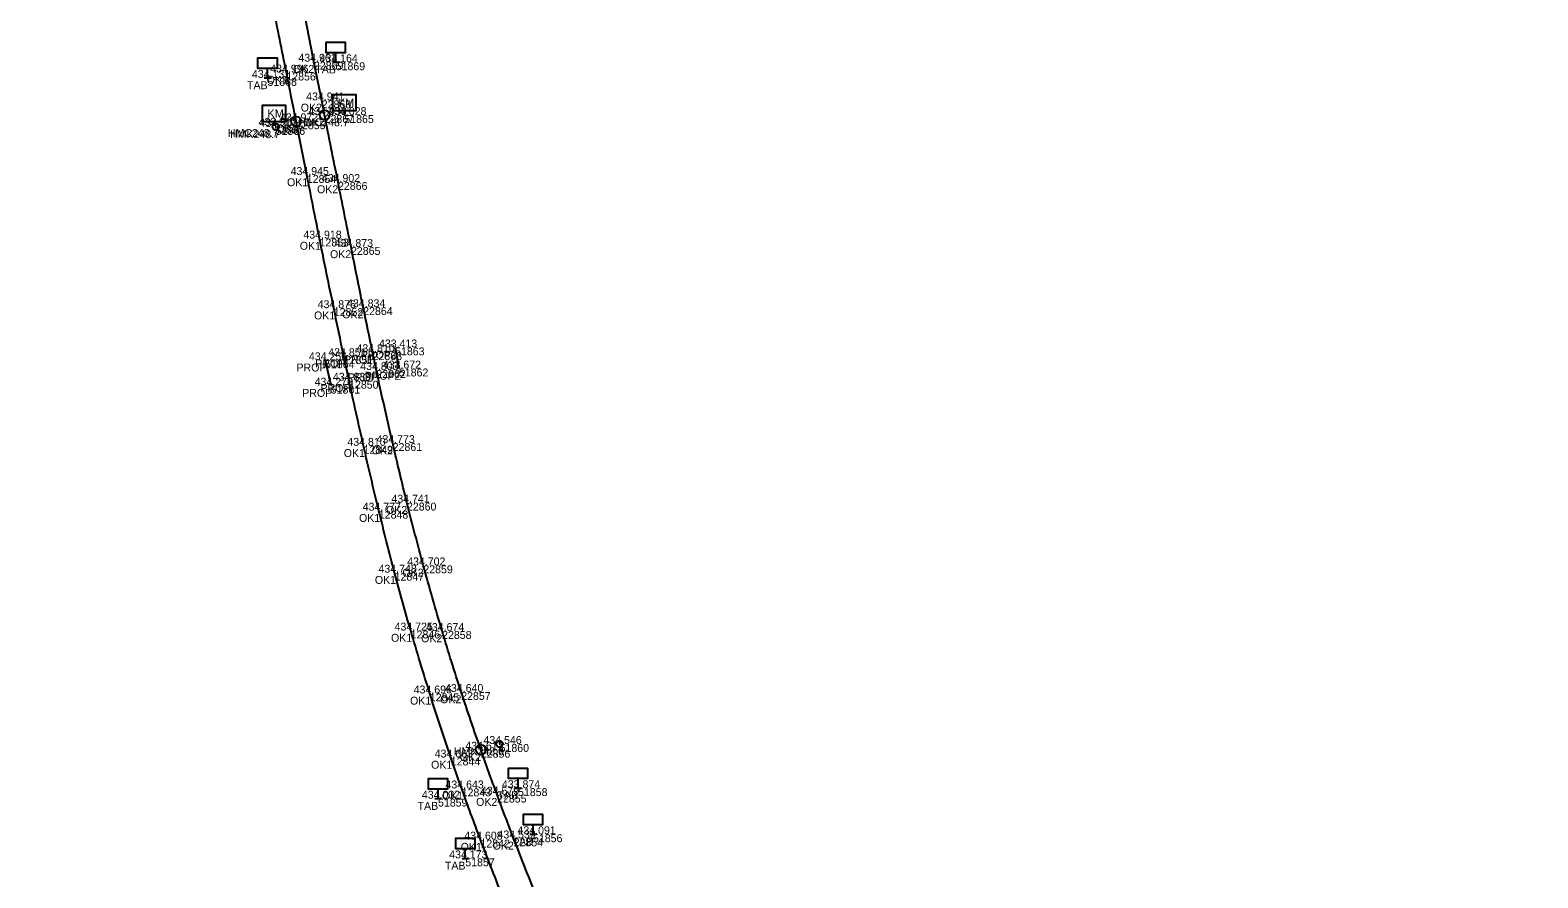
# Model space of a CAD drawing. Extents: x -678609 to -677678, y -1092434 to -1090394.
# Drawn here: x -678600.8 to -678372.1, y -1090904.4 to -1090775.9 of the extents above; entities that cross this region are included whole.
import ezdxf

# ---------------------------------------------------------------- set-up
doc = ezdxf.new("R2010")
doc.units = 0
for name, color, linetype in [('Vrstva 1', 7, 'Continuous'), ('Vrstva 19', 7, 'Continuous'), ('Vrstva 51', 7, 'Continuous'), ('Vrstva 60', 7, 'Continuous'), ('Vrstva 61', 7, 'Continuous'), ('Vrstva 62', 7, 'Continuous'), ('Vrstva 7', 7, 'Continuous')]:
    doc.layers.add(name, color=color, linetype=linetype)

msp = doc.modelspace()

# ---------------------------------------------------------------- linework, layer by layer
at = {"layer": 'Vrstva 1'}
for points in [[(-677965.5, -1092428.88), (-677967.8, -1092425.54), (-677972.06, -1092419.07), (-677977.32, -1092410.57), (-677981.84, -1092402.75), (-677986.7, -1092393.7), (-677991.48, -1092384.16), (-677995.99, -1092374.55), (-678000.17, -1092365.13), (-678004.02, -1092356.1), (-678007.82, -1092346.9), (-678011.74, -1092337.16), (-678015.49, -1092327.76), (-678018.88, -1092319.21), (-678022.34, -1092310.49), (-678025.4, -1092302.78), (-678026.46, -1092300.1), (-678028.08, -1092296.04), (-678031.51, -1092287.37), (-678035.08, -1092278.36), (-678038.67, -1092269.33), (-678042.19, -1092260.44), (-678045.92, -1092251.04), (-678049.17, -1092242.84), (-678052.72, -1092233.88), (-678056.52, -1092224.29), (-678060.13, -1092215.17), (-678063.85, -1092205.78), (-678067.58, -1092196.38), (-678071.23, -1092187.17), (-678074.63, -1092178.59), (-678078.07, -1092169.9), (-678081.19, -1092162.05), (-678084.71, -1092153.16), (-678085.21, -1092151.9), (-678088.66, -1092143.2), (-678090.49, -1092138.62), (-678093.75, -1092130.39), (-678097.35, -1092121.32), (-678101.03, -1092112.07), (-678104.65, -1092102.94), (-678108.08, -1092094.3), (-678111.85, -1092084.82), (-678115.34, -1092076.03), (-678118.88, -1092067.13), (-678122.7, -1092057.52), (-678126.45, -1092048.08), (-678130.12, -1092038.85), (-678134.04, -1092029), (-678137.7, -1092019.78), (-678141.32, -1092010.68), (-678144.94, -1092001.55), (-678148.54, -1091992.51), (-678152.22, -1091983.22), (-678155.78, -1091974.26), (-678159.37, -1091965.23), (-678163.15, -1091955.67), (-678166.8, -1091946.49), (-678170.64, -1091936.84), (-678174.45, -1091927.39), (-678178.21, -1091918.23), (-678182.03, -1091909.19), (-678185.86, -1091900.36), (-678190.3, -1091890.41), (-678194.61, -1091881.04), (-678198.42, -1091872.99), (-678201.55, -1091866.52), (-678205.76, -1091857.98), (-678210.04, -1091849.52), (-678214.14, -1091841.6), (-678218.68, -1091833.02), (-678223.39, -1091824.3), (-678228.11, -1091815.74), (-678232.89, -1091807.24), (-678237.68, -1091798.82), (-678242.57, -1091790.27), (-678247.48, -1091781.7), (-678252.5, -1091772.96), (-678257.41, -1091764.41), (-678262.3, -1091755.91), (-678267.38, -1091747.08), (-678272.06, -1091738.95), (-678276.67, -1091730.93), (-678281, -1091723.4), (-678285.64, -1091715.33), (-678290.57, -1091706.75), (-678295.17, -1091698.74), (-678299.18, -1091691.75), (-678304.61, -1091682.28), (-678309.18, -1091674.33), (-678309.94, -1091673.01), (-678310.56, -1091671.92), (-678316.58, -1091661.44), (-678321.55, -1091652.79), (-678326.07, -1091644.94), (-678331.1, -1091636.19), (-678336.13, -1091627.42), (-678341.16, -1091618.67), (-678346.24, -1091609.83), (-678351.2, -1091601.19), (-678356.26, -1091592.39), (-678361.27, -1091583.68), (-678366.29, -1091574.95), (-678371.38, -1091566.09), (-678376.48, -1091557.23), (-678380.94, -1091549.47), (-678384.95, -1091542.5), (-678389.88, -1091533.92), (-678391.41, -1091531.24), (-678395.31, -1091524.46), (-678398.31, -1091519.22), (-678402.19, -1091512.46), (-678406.98, -1091504.09), (-678412.06, -1091495.21), (-678417.07, -1091486.44), (-678421.59, -1091478.47), (-678426.39, -1091469.86), (-678431.19, -1091461.01), (-678435.59, -1091452.6), (-678440.54, -1091442.69), (-678444.84, -1091433.53), (-678448.93, -1091424.07), (-678452.67, -1091414.65), (-678456.15, -1091404.93), (-678459.23, -1091395.35), (-678461.83, -1091386.29), (-678463.33, -1091380.53), (-678465.42, -1091371.56), (-678467.31, -1091362.18), (-678468.87, -1091352.97), (-678470.15, -1091343.72), (-678471.15, -1091334.55), (-678471.89, -1091325.25), (-678472.38, -1091315.14), (-678472.53, -1091305.81), (-678472.39, -1091295.81), (-678471.98, -1091285.84), (-678471.34, -1091275.9), (-678470.53, -1091266.07), (-678469.61, -1091256.67), (-678468.46, -1091246.14), (-678467.2, -1091235.36), (-678466.06, -1091225.73), (-678464.97, -1091216.57), (-678463.79, -1091206.63), (-678462.6, -1091196.46), (-678461.48, -1091186.51), (-678460.53, -1091177.26), (-678460.07, -1091172.27), (-678459.6, -1091166.76), (-678458.93, -1091157.15), (-678458.54, -1091149.43), (-678458.26, -1091139.81), (-678458.24, -1091130.03), (-678458.46, -1091121.76), (-678458.96, -1091112.72), (-678459.56, -1091105.42), (-678460.03, -1091100.7), (-678460.44, -1091097.18), (-678461.42, -1091089.83), (-678462.92, -1091080.59), (-678464.88, -1091070.5), (-678465.87, -1091066.01), (-678468.24, -1091056.34), (-678470.96, -1091046.62), (-678473.78, -1091037.66), (-678476.99, -1091028.33), (-678480.32, -1091019.35), (-678483.95, -1091010.17), (-678487.77, -1091000.93), (-678492.09, -1090990.94), (-678495.91, -1090982.33), (-678497.23, -1090979.39), (-678500.62, -1090971.85), (-678504.73, -1090962.75), (-678508.48, -1090954.44), (-678512.89, -1090944.72), (-678517.19, -1090935.17), (-678521.19, -1090926.12), (-678525.01, -1090917.23), (-678528.92, -1090907.75), (-678532.48, -1090898.64), (-678535.33, -1090890.88), (-678536.98, -1090886.19), (-678540.17, -1090876.47), (-678543.06, -1090866.93), (-678545.5, -1090858.15), (-678547.9, -1090848.75), (-678550.22, -1090838.91), (-678552.41, -1090829.04), (-678553.21, -1090825.32), (-678554.73, -1090818.04), (-678556.89, -1090807.48), (-678558.82, -1090797.84), (-678560.45, -1090789.69), (-678561.92, -1090782.3), (-678563.92, -1090772.26), (-678565.62, -1090763.66), (-678567.4, -1090754.78), (-678569.24, -1090745.59), (-678571.09, -1090736.37), (-678573.01, -1090726.79), (-678574.94, -1090717.24), (-678576.9, -1090707.5), (-678578.79, -1090698.06), (-678580.69, -1090688.61), (-678582.63, -1090679), (-678584.57, -1090669.32), (-678586.61, -1090659.12), (-678588.6, -1090649.18), (-678590.47, -1090639.75), (-678592.41, -1090629.68), (-678594.08, -1090620.48), (-678595.57, -1090611.73), (-678596.96, -1090602.7), (-678598.18, -1090593.61), (-678598.92, -1090587.15), (-678599.86, -1090577.04), (-678600.45, -1090567.62), (-678600.74, -1090558.34), (-678600.75, -1090549.35), (-678600.47, -1090539.84), (-678599.88, -1090530.15), (-678599.15, -1090521.99), (-678598.15, -1090513.61), (-678597.58, -1090509.5), (-678596.28, -1090501.33), (-678594.49, -1090491.96), (-678592.38, -1090482.44), (-678589.8, -1090472.45), (-678586.94, -1090462.72), (-678583.68, -1090452.87), (-678579.95, -1090442.85), (-678576.03, -1090433.29), (-678571.81, -1090423.92), (-678567.43, -1090415), (-678562.94, -1090406.55), (-678558.47, -1090398.73), (-678556.06, -1090394.72)], [(-677960.41, -1092428.88), (-677963.18, -1092424.89), (-677968.58, -1092416.71), (-677973.83, -1092408.16), (-677978.65, -1092399.73), (-677983.17, -1092391.19), (-677987.58, -1092382.29), (-677991.66, -1092373.51), (-677995.54, -1092364.73), (-677999.48, -1092355.45), (-678003, -1092346.86), (-678006.4, -1092338.41), (-678008.07, -1092334.22), (-678011.06, -1092326.67), (-678014.79, -1092317.28), (-678018.17, -1092308.77), (-678021.37, -1092300.71), (-678022.15, -1092298.75), (-678025.47, -1092290.39), (-678029, -1092281.48), (-678032.79, -1092271.95), (-678036.42, -1092262.78), (-678040.08, -1092253.55), (-678043.64, -1092244.58), (-678046.8, -1092236.63), (-678050.2, -1092228.09), (-678054.05, -1092218.4), (-678057.87, -1092208.77), (-678061.64, -1092199.28), (-678064.93, -1092190.99), (-678068.51, -1092181.96), (-678072.17, -1092172.75), (-678076, -1092163.12), (-678079.45, -1092154.42), (-678082.71, -1092146.18), (-678084.42, -1092141.9), (-678086.21, -1092137.37), (-678089.72, -1092128.54), (-678093.32, -1092119.46), (-678097.16, -1092109.8), (-678100.72, -1092100.82), (-678103.85, -1092092.93), (-678107.35, -1092084.1), (-678110.92, -1092075.12), (-678114.45, -1092066.22), (-678118.41, -1092056.23), (-678122.02, -1092047.13), (-678125.64, -1092038.01), (-678129.26, -1092028.91), (-678132.87, -1092019.79), (-678136.68, -1092010.21), (-678140.28, -1092001.13), (-678143.89, -1091992.04), (-678147.54, -1091982.83), (-678151.47, -1091972.91), (-678155.19, -1091963.55), (-678158.5, -1091955.23), (-678162.14, -1091946.1), (-678165.94, -1091936.55), (-678169.61, -1091927.42), (-678172.98, -1091919.18), (-678176.44, -1091910.89), (-678180.32, -1091901.84), (-678184.49, -1091892.39), (-678188.93, -1091882.59), (-678193.21, -1091873.41), (-678197.78, -1091863.91), (-678202.15, -1091855.03), (-678206.56, -1091846.3), (-678211.05, -1091837.64), (-678215.66, -1091828.96), (-678220.33, -1091820.38), (-678225.04, -1091811.91), (-678229.83, -1091803.42), (-678234.98, -1091794.42), (-678239.05, -1091787.33), (-678241.84, -1091782.5), (-678246.33, -1091774.68), (-678251.23, -1091766.16), (-678256.35, -1091757.27), (-678261.45, -1091748.4), (-678266.63, -1091739.38), (-678271.03, -1091731.75), (-678275.99, -1091723.11), (-678281.08, -1091714.25), (-678285.98, -1091705.75), (-678290.88, -1091697.22), (-678295.45, -1091689.28), (-678300.01, -1091681.35), (-678300.91, -1091679.77), (-678305.04, -1091672.59), (-678308.7, -1091666.23), (-678313.56, -1091657.79), (-678316.07, -1091653.42), (-678316.99, -1091651.81), (-678322.04, -1091643.03), (-678327.11, -1091634.21), (-678332.27, -1091625.24), (-678337.32, -1091616.47), (-678342.33, -1091607.74), (-678347.33, -1091599.07), (-678352.43, -1091590.19), (-678357.51, -1091581.37), (-678362.52, -1091572.64), (-678367.56, -1091563.89), (-678372.6, -1091555.12), (-678377.69, -1091546.26), (-678382.67, -1091537.58), (-678387.77, -1091528.7), (-678389.17, -1091526.27), (-678390.17, -1091524.53), (-678393.18, -1091519.29), (-678397.89, -1091511.08), (-678402.8, -1091502.52), (-678408.01, -1091493.44), (-678412.94, -1091484.8), (-678417.67, -1091476.44), (-678422.72, -1091467.34), (-678425.17, -1091462.84), (-678430.24, -1091453.27), (-678432.13, -1091449.6), (-678436.36, -1091441.06), (-678440.36, -1091432.52), (-678444.3, -1091423.5), (-678448.14, -1091413.92), (-678451.67, -1091404.2), (-678454.52, -1091395.48), (-678456.78, -1091387.89), (-678459.36, -1091378.14), (-678461.46, -1091369.04), (-678463.24, -1091360.11), (-678464.77, -1091350.94), (-678466.09, -1091341.11), (-678467.05, -1091331.45), (-678467.74, -1091321.16), (-678468.06, -1091312.46), (-678468.13, -1091302.67), (-678467.92, -1091292.89), (-678467.75, -1091288.5), (-678467.24, -1091279.36), (-678466.65, -1091271.3), (-678465.8, -1091261.65), (-678464.83, -1091252.21), (-678464.22, -1091246.73), (-678463.17, -1091237.54), (-678462.04, -1091228.08), (-678460.89, -1091218.47), (-678459.79, -1091209.09), (-678458.69, -1091199.72), (-678457.61, -1091190.23), (-678456.66, -1091181.26), (-678456.28, -1091177.45), (-678455.95, -1091173.93), (-678455.21, -1091164.81), (-678454.58, -1091155.4), (-678454.12, -1091145.39), (-678453.9, -1091135.42), (-678453.98, -1091125.41), (-678454.4, -1091115.15), (-678455.19, -1091104.66), (-678455.67, -1091099.79), (-678456.77, -1091090.92), (-678457.24, -1091087.61), (-678458, -1091082.76), (-678459.78, -1091072.93), (-678461.55, -1091064.59), (-678463.75, -1091055.56), (-678466.3, -1091046.3), (-678469.14, -1091037.12), (-678472.3, -1091027.84), (-678475.73, -1091018.55), (-678479.35, -1091009.34), (-678482.78, -1091001.05), (-678486.39, -1090992.59), (-678490.2, -1090983.9), (-678491.75, -1090980.39), (-678492.98, -1090977.64), (-678496.18, -1090970.51), (-678500.43, -1090961.06), (-678504.03, -1090953.05), (-678508.11, -1090943.95), (-678512.14, -1090934.91), (-678516.17, -1090925.76), (-678520.15, -1090916.48), (-678524.11, -1090906.91), (-678527.45, -1090898.46), (-678529.96, -1090891.82), (-678532.42, -1090885.01), (-678535.4, -1090876.25), (-678538.3, -1090867), (-678541.15, -1090857.05), (-678543.63, -1090847.53), (-678545.8, -1090838.5), (-678548.27, -1090827.42), (-678548.84, -1090824.71), (-678550.27, -1090817.89), (-678552.12, -1090808.75), (-678554.09, -1090798.9), (-678556.12, -1090788.74), (-678556.56, -1090786.52), (-678557.74, -1090780.65), (-678559.41, -1090772.28), (-678561.24, -1090763.16), (-678563.16, -1090753.57), (-678565.21, -1090743.33), (-678567.13, -1090733.77), (-678569.13, -1090723.69), (-678570.72, -1090715.75), (-678572.44, -1090707.11), (-678574.33, -1090697.58), (-678575.5, -1090691.73), (-678576.87, -1090684.87), (-678578.68, -1090675.8), (-678580.42, -1090667.12), (-678582.34, -1090657.49), (-678584.31, -1090647.61), (-678586.28, -1090637.64), (-678588.2, -1090627.59), (-678589.96, -1090617.89), (-678591.58, -1090608.06), (-678593.06, -1090598.01), (-678594.31, -1090587.86), (-678595.29, -1090577.74), (-678595.95, -1090567.92), (-678596.27, -1090558.34), (-678596.28, -1090548.9), (-678595.99, -1090539.16), (-678595.39, -1090529.68), (-678594.52, -1090520.33), (-678593.84, -1090514.64), (-678593.37, -1090511.09), (-678591.87, -1090501.55), (-678590.51, -1090494.26), (-678588.64, -1090485.54), (-678587.94, -1090482.56), (-678585.53, -1090473.2), (-678582.78, -1090463.82), (-678579.92, -1090455.12), (-678576.62, -1090446.03), (-678572.81, -1090436.54), (-678568.84, -1090427.54), (-678564.34, -1090418.19), (-678559.62, -1090409.18), (-678555.08, -1090401.15), (-678551.2, -1090394.72)]]:
    msp.add_spline(points, degree=3, dxfattribs=at)
at = {"layer": 'Vrstva 19'}
for p, q in [((-678545.43, -1090823.99), (-678544.85, -1090827.19)), ((-678556.06, -1090825.94), (-678555.19, -1090829.79))]:
    msp.add_line(p, q, dxfattribs=at)
at = {"layer": 'Vrstva 51'}
for p, q in [((-678554.94, -1090780.74), (-678553.94, -1090780.74)), ((-678565.29, -1090783.12), (-678564.29, -1090783.12)), ((-678527.28, -1090890.84), (-678526.28, -1090890.84)), ((-678539.42, -1090892.43), (-678538.42, -1090892.43)), ((-678525.01, -1090897.83), (-678524.01, -1090897.83)), ((-678535.28, -1090901.49), (-678534.28, -1090901.49))]:
    msp.add_line(p, q, dxfattribs=at)
for points in [[(-678554.44, -1090780.74), (-678554.44, -1090779.24), (-678552.94, -1090779.24), (-678552.94, -1090777.74), (-678555.94, -1090777.74), (-678555.94, -1090779.24), (-678554.44, -1090779.24)], [(-678564.79, -1090783.12), (-678564.79, -1090781.62), (-678563.29, -1090781.62), (-678563.29, -1090780.12), (-678566.29, -1090780.12), (-678566.29, -1090781.62), (-678564.79, -1090781.62)], [(-678526.78, -1090890.84), (-678526.78, -1090889.34), (-678525.28, -1090889.34), (-678525.28, -1090887.84), (-678528.28, -1090887.84), (-678528.28, -1090889.34), (-678526.78, -1090889.34)], [(-678538.92, -1090892.43), (-678538.92, -1090890.93), (-678537.42, -1090890.93), (-678537.42, -1090889.43), (-678540.42, -1090889.43), (-678540.42, -1090890.93), (-678538.92, -1090890.93)], [(-678524.51, -1090897.83), (-678524.51, -1090896.33), (-678523.01, -1090896.33), (-678523.01, -1090894.83), (-678526.01, -1090894.83), (-678526.01, -1090896.33), (-678524.51, -1090896.33)], [(-678534.78, -1090901.49), (-678534.78, -1090899.99), (-678533.28, -1090899.99), (-678533.28, -1090898.49), (-678536.28, -1090898.49), (-678536.28, -1090899.99), (-678534.78, -1090899.99)]]:
    msp.add_lwpolyline(points, dxfattribs=at)
at = {"layer": 'Vrstva 60'}
for p, q in [((-678557.74, -1090780.65), (-678557.74, -1090780.65)), ((-678554.44, -1090780.74), (-678554.44, -1090780.74)), ((-678564.79, -1090783.12), (-678564.79, -1090783.12)), ((-678561.92, -1090782.3), (-678561.92, -1090782.3)), ((-678556.56, -1090786.52), (-678556.56, -1090786.52)), ((-678560.45, -1090789.69), (-678560.45, -1090789.69)), ((-678556.12, -1090788.74), (-678556.12, -1090788.74)), ((-678553.13, -1090788.75), (-678553.13, -1090788.75)), ((-678563.78, -1090790.37), (-678563.78, -1090790.37)), ((-678563.54, -1090790.55), (-678563.54, -1090790.55)), ((-678558.82, -1090797.84), (-678558.82, -1090797.84)), ((-678554.09, -1090798.9), (-678554.09, -1090798.9)), ((-678556.89, -1090807.48), (-678556.89, -1090807.48)), ((-678552.12, -1090808.75), (-678552.12, -1090808.75)), ((-678554.73, -1090818.04), (-678554.73, -1090818.04)), ((-678550.27, -1090817.89), (-678550.27, -1090817.89)), ((-678545.43, -1090823.99), (-678545.43, -1090823.99)), ((-678556.06, -1090825.94), (-678556.06, -1090825.94)), ((-678553.21, -1090825.32), (-678553.21, -1090825.32)), ((-678548.84, -1090824.71), (-678548.84, -1090824.71)), ((-678552.41, -1090829.04), (-678552.41, -1090829.04)), ((-678548.27, -1090827.42), (-678548.27, -1090827.42)), ((-678544.85, -1090827.19), (-678544.85, -1090827.19)), ((-678555.19, -1090829.79), (-678555.19, -1090829.79)), ((-678550.22, -1090838.91), (-678550.22, -1090838.91)), ((-678545.8, -1090838.5), (-678545.8, -1090838.5)), ((-678543.63, -1090847.53), (-678543.63, -1090847.53)), ((-678547.9, -1090848.75), (-678547.9, -1090848.75)), ((-678545.5, -1090858.15), (-678545.5, -1090858.15)), ((-678541.15, -1090857.05), (-678541.15, -1090857.05)), ((-678543.06, -1090866.93), (-678543.06, -1090866.93)), ((-678538.3, -1090867), (-678538.3, -1090867)), ((-678540.17, -1090876.47), (-678540.17, -1090876.47)), ((-678535.4, -1090876.25), (-678535.4, -1090876.25)), ((-678536.98, -1090886.19), (-678536.98, -1090886.19)), ((-678532.42, -1090885.01), (-678532.42, -1090885.01)), ((-678529.58, -1090884.14), (-678529.58, -1090884.14)), ((-678535.33, -1090890.88), (-678535.33, -1090890.88)), ((-678526.78, -1090890.84), (-678526.78, -1090890.84)), ((-678538.92, -1090892.43), (-678538.92, -1090892.43)), ((-678529.96, -1090891.82), (-678529.96, -1090891.82)), ((-678524.51, -1090897.83), (-678524.51, -1090897.83)), ((-678532.48, -1090898.64), (-678532.48, -1090898.64)), ((-678527.45, -1090898.46), (-678527.45, -1090898.46)), ((-678534.78, -1090901.49), (-678534.78, -1090901.49))]:
    msp.add_line(p, q, dxfattribs=at)
at = {"layer": 'Vrstva 7'}
for p, q in [((-678563.78, -1090790.37), (-678563.78, -1090789.75)), ((-678553.13, -1090788.75), (-678553.13, -1090788.13)), ((-678563.59, -1090790.55), (-678563.49, -1090790.55)), ((-678529.63, -1090884.14), (-678529.53, -1090884.14))]:
    msp.add_line(p, q, dxfattribs=at)
for points in [[(-678554.87, -1090788.13), (-678554.87, -1090785.65), (-678551.38, -1090785.65), (-678551.38, -1090788.13)], [(-678565.53, -1090789.75), (-678565.53, -1090787.27), (-678562.04, -1090787.27), (-678562.04, -1090789.75)]]:
    msp.add_lwpolyline(points, close=True, dxfattribs=at)
for centre, radius in [((-678556.12, -1090788.74), 0.75), ((-678563.54, -1090790.55), 0.5), ((-678560.45, -1090789.69), 0.75), ((-678529.58, -1090884.14), 0.5), ((-678532.42, -1090885.01), 0.75)]:
    msp.add_circle(centre, radius, dxfattribs=at)

# ---------------------------------------------------------------- texts
at = {"layer": 'Vrstva 60'}
for s, p in [('22869', (-678557.74, -1090781.85)), ('51869', (-678554.44, -1090781.94)), ('51868', (-678564.79, -1090784.32)), ('12856', (-678561.92, -1090783.5)), ('22868', (-678556.56, -1090787.72)), ('51867', (-678563.78, -1090791.57)), ('12855', (-678560.45, -1090790.89)), ('22867', (-678556.12, -1090789.94)), ('51865', (-678553.13, -1090789.95)), ('51866', (-678563.54, -1090791.75)), ('12854', (-678558.82, -1090799.04)), ('22866', (-678554.09, -1090800.1)), ('12853', (-678556.89, -1090808.68)), ('22865', (-678552.12, -1090809.95)), ('12852', (-678554.73, -1090819.24)), ('22864', (-678550.27, -1090819.08)), ('51863', (-678545.43, -1090825.19)), ('51864', (-678556.06, -1090827.14)), ('12851', (-678553.21, -1090826.52)), ('22863', (-678548.84, -1090825.91)), ('12850', (-678552.41, -1090830.24)), ('22862', (-678548.27, -1090828.62)), ('51862', (-678544.85, -1090828.39)), ('51861', (-678555.19, -1090830.99)), ('12849', (-678550.22, -1090840.11)), ('22861', (-678545.8, -1090839.7)), ('22860', (-678543.63, -1090848.73)), ('12848', (-678547.9, -1090849.95)), ('12847', (-678545.5, -1090859.35)), ('22859', (-678541.15, -1090858.25)), ('12846', (-678543.06, -1090868.13)), ('22858', (-678538.3, -1090868.2)), ('12845', (-678540.17, -1090877.67)), ('22857', (-678535.4, -1090877.45)), ('51860', (-678529.58, -1090885.34)), ('12844', (-678536.98, -1090887.39)), ('22856', (-678532.42, -1090886.21)), ('12843', (-678535.33, -1090892.08)), ('51858', (-678526.78, -1090892.04)), ('51859', (-678538.92, -1090893.63)), ('22855', (-678529.96, -1090893.02)), ('51856', (-678524.51, -1090899.03)), ('12842', (-678532.48, -1090899.84)), ('22854', (-678527.45, -1090899.66)), ('51857', (-678534.78, -1090902.69))]:
    msp.add_text(s, height=1.2, dxfattribs=at).set_placement(p)
at = {"layer": 'Vrstva 61'}
for s, p in [('434.996', (-678564.37, -1090782.3)), ('434.961', (-678560.1, -1090780.65)), ('434.164', (-678556.89, -1090780.74)), ('434.131', (-678567.15, -1090783.12)), ('434.941', (-678558.92, -1090786.52)), ('434.933', (-678558.58, -1090788.74)), ('434.028', (-678555.58, -1090788.75)), ('433.911', (-678566.14, -1090790.37)), ('434.503', (-678565.99, -1090790.55)), ('434.972', (-678562.9, -1090789.69)), ('434.945', (-678561.28, -1090797.84)), ('434.902', (-678556.54, -1090798.9)), ('434.918', (-678559.34, -1090807.48)), ('434.873', (-678554.58, -1090808.75)), ('434.876', (-678557.18, -1090818.04)), ('434.834', (-678552.72, -1090817.89)), ('434.851', (-678555.57, -1090825.32)), ('434.810', (-678551.29, -1090824.71)), ('433.413', (-678547.88, -1090823.99)), ('434.256', (-678558.51, -1090825.94)), ('434.803', (-678550.72, -1090827.42)), ('433.672', (-678547.3, -1090827.19)), ('434.276', (-678557.64, -1090829.79)), ('434.839', (-678554.87, -1090829.04)), ('434.810', (-678552.67, -1090838.91)), ('434.773', (-678548.25, -1090838.5)), ('434.777', (-678550.35, -1090848.75)), ('434.741', (-678545.99, -1090847.53)), ('434.702', (-678543.6, -1090857.05)), ('434.748', (-678547.95, -1090858.15)), ('434.725', (-678545.51, -1090866.93)), ('434.674', (-678540.75, -1090867)), ('434.696', (-678542.62, -1090876.47)), ('434.640', (-678537.85, -1090876.25)), ('434.611', (-678534.78, -1090885.01)), ('434.546', (-678532.03, -1090884.14)), ('434.663', (-678539.43, -1090886.19)), ('434.643', (-678537.79, -1090890.88)), ('434.579', (-678532.42, -1090891.82)), ('433.874', (-678529.23, -1090890.84)), ('434.032', (-678541.37, -1090892.43)), ('434.608', (-678534.93, -1090898.64)), ('434.532', (-678529.9, -1090898.46)), ('434.091', (-678526.87, -1090897.83)), ('434.173', (-678537.23, -1090901.49))]:
    msp.add_text(s, height=1.2, dxfattribs=at).set_placement(p)
at = {"layer": 'Vrstva 62'}
for s, p in [('OK2', (-678560.92, -1090782.35)), ('OK1', (-678564.92, -1090784)), ('TAB', (-678557.54, -1090782.44)), ('TAB', (-678567.89, -1090784.82)), ('OK2', (-678559.74, -1090788.22)), ('OK1', (-678563.45, -1090791.39)), ('HMC248.7', (-678560.13, -1090790.45)), ('OK2', (-678559.3, -1090790.44)), ('HMC248.7', (-678570.79, -1090792.07)), ('HMK248.7', (-678570.47, -1090792.25)), ('OK1', (-678561.82, -1090799.54)), ('OK2', (-678557.27, -1090800.6)), ('OK1', (-678559.89, -1090809.18)), ('OK2', (-678555.3, -1090810.45)), ('OK1', (-678557.73, -1090819.74)), ('OK2', (-678553.45, -1090819.58)), ('PROPZ', (-678550.63, -1090825.69)), ('PROP', (-678560.39, -1090827.64)), ('PROP', (-678557.54, -1090827.02)), ('PROP', (-678553.18, -1090826.41)), ('PROP', (-678552.6, -1090829.12)), ('PROPZ', (-678550.05, -1090828.89)), ('PROP', (-678559.52, -1090831.49)), ('PROP', (-678556.75, -1090830.74)), ('OK1', (-678553.22, -1090840.61)), ('OK2', (-678548.98, -1090840.2)), ('OK1', (-678550.9, -1090850.45)), ('OK2', (-678546.81, -1090849.23)), ('OK1', (-678548.5, -1090859.85)), ('OK2', (-678544.33, -1090858.75)), ('OK1', (-678546.05, -1090868.63)), ('OK2', (-678541.48, -1090868.7)), ('OK1', (-678543.17, -1090878.17)), ('OK2', (-678538.58, -1090877.95)), ('HMK248.6', (-678536.51, -1090885.84)), ('OK2', (-678535.6, -1090886.71)), ('OK1', (-678539.97, -1090887.89)), ('TAB', (-678542.02, -1090894.13)), ('OK1', (-678538.33, -1090892.58)), ('OK2', (-678533.14, -1090893.52)), ('TAB', (-678529.88, -1090892.54)), ('OK1', (-678535.48, -1090900.34)), ('OK2', (-678530.63, -1090900.16)), ('TAB', (-678527.61, -1090899.53)), ('TAB', (-678537.88, -1090903.19))]:
    msp.add_text(s, height=1.2, dxfattribs=at).set_placement(p)
at = {"layer": 'Vrstva 7'}
for p in [(-678564.8, -1090789.13), (-678554.14, -1090787.51)]:
    msp.add_text('KM', height=1.247, dxfattribs=at).set_placement(p)

doc.saveas('drawing.dxf')
